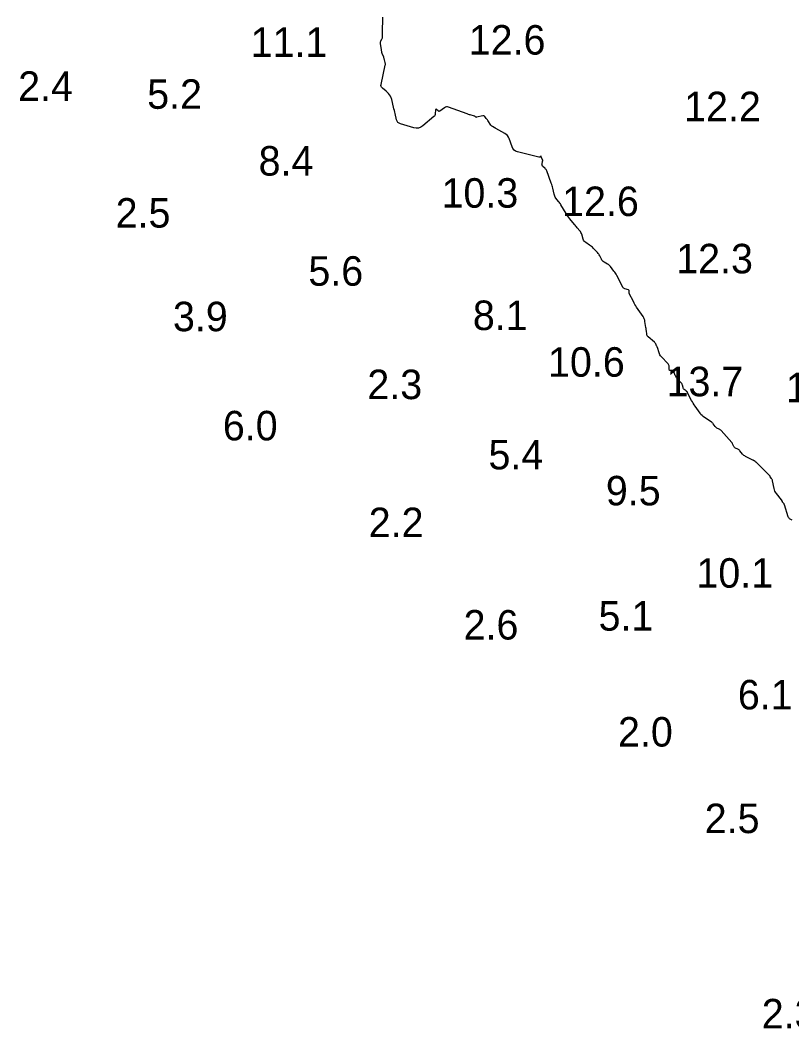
# Model space of a CAD drawing. Extents: x 815352 to 820877, y 582403 to 597439.
# Drawn here: x 819118.2 to 819249.1, y 593792.3 to 593963.3 of the extents above; entities that cross this region are included whole.
import ezdxf

# ---------------------------------------------------------------- set-up
doc = ezdxf.new("R2010")
doc.units = 0
doc.layers.add('V-CONT-EL12', color=7, linetype='Continuous')
doc.layers.add('V-TOPO-SOUN', color=7, linetype='Continuous')

msp = doc.modelspace()

# ---------------------------------------------------------------- linework, layer by layer
at = {"layer": 'V-CONT-EL12'}
msp.add_lwpolyline([(819249.13, 593878.51), (819248.72, 593878.76), (819248.63, 593878.83), (819248.56, 593878.9), (819248.5, 593878.99), (819248.46, 593879.09), (819247.83, 593881.13), (819247.81, 593881.18), (819247.79, 593881.23), (819247.76, 593881.28), (819247.73, 593881.32), (819247.56, 593881.52), (819247.54, 593881.56), (819247.51, 593881.59), (819247.49, 593881.63), (819247.48, 593881.67), (819247.42, 593881.83), (819247.4, 593881.87), (819247.38, 593881.91), (819247.36, 593881.94), (819247.34, 593881.98), (819246.47, 593883.05), (819246.33, 593883.24), (819246.22, 593883.45), (819246.13, 593883.67), (819246.07, 593883.9), (819245.81, 593885.19), (819245.79, 593885.29), (819245.75, 593885.38), (819245.71, 593885.47), (819245.66, 593885.55), (819245.44, 593885.88), (819245.39, 593885.97), (819245.33, 593886.04), (819245.26, 593886.12), (819245.19, 593886.19), (819243.07, 593888.28), (819243.03, 593888.32), (819242.98, 593888.36), (819242.93, 593888.4), (819242.88, 593888.44), (819242.68, 593888.58), (819242.63, 593888.62), (819242.58, 593888.65), (819242.52, 593888.68), (819242.47, 593888.71), (819241.24, 593889.32), (819241.1, 593889.4), (819240.97, 593889.49), (819240.85, 593889.59), (819240.74, 593889.71), (819240.27, 593890.28), (819240.2, 593890.36), (819240.12, 593890.43), (819240.03, 593890.49), (819239.93, 593890.54), (819239.53, 593890.73), (819239.44, 593890.78), (819239.37, 593890.84), (819239.31, 593890.92), (819239.26, 593891), (819239.1, 593891.36), (819239.05, 593891.45), (819239, 593891.53), (819238.95, 593891.61), (819238.89, 593891.69), (819237.11, 593893.69), (819237.03, 593893.77), (819236.95, 593893.84), (819236.86, 593893.9), (819236.77, 593893.95), (819236.38, 593894.13), (819236.29, 593894.19), (819236.2, 593894.25), (819236.13, 593894.32), (819236.06, 593894.4), (819235.76, 593894.83), (819235.68, 593894.93), (819235.6, 593895.02), (819235.51, 593895.1), (819235.41, 593895.17), (819234.28, 593895.92), (819234.06, 593896.08), (819233.87, 593896.26), (819233.68, 593896.45), (819233.52, 593896.66), (819232.67, 593897.86), (819232.52, 593898.09), (819232.37, 593898.32), (819232.23, 593898.56), (819232.1, 593898.81), (819231.42, 593900.1), (819231.37, 593900.19), (819231.31, 593900.27), (819231.24, 593900.34), (819231.17, 593900.41), (819230.85, 593900.66), (819230.78, 593900.72), (819230.72, 593900.8), (819230.68, 593900.88), (819230.65, 593900.98), (819230.54, 593901.4), (819230.51, 593901.5), (819230.47, 593901.59), (819230.42, 593901.68), (819230.35, 593901.76), (819229.65, 593902.53), (819229.55, 593902.64), (819229.46, 593902.77), (819229.39, 593902.9), (819229.33, 593903.04), (819229.06, 593903.74), (819229.02, 593903.81), (819228.97, 593903.85), (819228.91, 593903.88), (819228.83, 593903.89), (819228.48, 593903.87), (819228.41, 593903.88), (819228.35, 593903.9), (819228.32, 593903.96), (819228.31, 593904.03), (819228.3, 593904.58), (819228.29, 593904.7), (819228.25, 593904.81), (819228.2, 593904.91), (819228.13, 593905), (819226.95, 593906.25), (819226.83, 593906.39), (819226.73, 593906.54), (819226.65, 593906.7), (819226.58, 593906.87), (819226.29, 593907.76), (819226.26, 593907.84), (819226.23, 593907.92), (819226.2, 593908), (819226.16, 593908.08), (819226, 593908.4), (819225.96, 593908.47), (819225.91, 593908.54), (819225.85, 593908.61), (819225.79, 593908.67), (819224.73, 593909.57), (819224.64, 593909.67), (819224.56, 593909.78), (819224.51, 593909.9), (819224.49, 593910.03), (819224.42, 593910.59), (819224.4, 593910.73), (819224.38, 593910.87), (819224.36, 593911.01), (819224.34, 593911.15), (819224.18, 593912.2), (819224.14, 593912.42), (819224.07, 593912.62), (819223.97, 593912.82), (819223.86, 593913.01), (819222.77, 593914.59), (819222.61, 593914.82), (819222.47, 593915.06), (819222.33, 593915.3), (819222.21, 593915.55), (819221.52, 593916.95), (819221.5, 593917), (819221.49, 593917.06), (819221.48, 593917.11), (819221.48, 593917.17), (819221.49, 593917.39), (819221.49, 593917.44), (819221.47, 593917.48), (819221.44, 593917.51), (819221.39, 593917.54), (819220.78, 593917.73), (819220.67, 593917.77), (819220.57, 593917.84), (819220.49, 593917.92), (819220.42, 593918.02), (819219.39, 593920.01), (819219.28, 593920.2), (819219.17, 593920.38), (819219.05, 593920.56), (819218.92, 593920.73), (819218.33, 593921.49), (819218.22, 593921.62), (819218.1, 593921.73), (819217.97, 593921.84), (819217.83, 593921.93), (819217.25, 593922.26), (819217.11, 593922.35), (819216.99, 593922.46), (819216.89, 593922.58), (819216.81, 593922.73), (819216.51, 593923.32), (819216.43, 593923.46), (819216.34, 593923.6), (819216.24, 593923.73), (819216.13, 593923.86), (819215.4, 593924.64), (819215.26, 593924.78), (819215.11, 593924.91), (819214.96, 593925.03), (819214.8, 593925.14), (819214.14, 593925.58), (819213.99, 593925.69), (819213.87, 593925.83), (819213.77, 593925.99), (819213.7, 593926.17), (819213.45, 593926.97), (819213.39, 593927.13), (819213.32, 593927.28), (819213.23, 593927.43), (819213.13, 593927.56), (819212.69, 593928.09), (819212.58, 593928.22), (819212.47, 593928.36), (819212.36, 593928.49), (819212.25, 593928.62), (819211.43, 593929.61), (819211.26, 593929.82), (819211.1, 593930.04), (819210.95, 593930.26), (819210.8, 593930.49), (819209.94, 593931.95), (819209.84, 593932.11), (819209.74, 593932.26), (819209.64, 593932.4), (819209.53, 593932.55), (819209.07, 593933.11), (819208.97, 593933.26), (819208.88, 593933.42), (819208.82, 593933.58), (819208.77, 593933.75), (819208.54, 593934.76), (819208.49, 593934.99), (819208.43, 593935.21), (819208.36, 593935.43), (819208.28, 593935.65), (819207.52, 593937.7), (819207.47, 593937.82), (819207.41, 593937.93), (819207.33, 593938.03), (819207.25, 593938.13), (819206.82, 593938.54), (819206.77, 593938.61), (819206.73, 593938.68), (819206.71, 593938.76), (819206.72, 593938.85), (819206.8, 593939.38), (819206.81, 593939.39), (819206.81, 593939.4), (819206.82, 593939.41), (819206.83, 593939.42), (819206.87, 593939.45), (819206.88, 593939.46), (819206.88, 593939.47), (819206.89, 593939.48), (819206.88, 593939.49), (819206.65, 593939.96), (819206.63, 593939.98), (819206.62, 593940.01), (819206.61, 593940.03), (819206.6, 593940.06), (819206.57, 593940.16), (819206.56, 593940.18), (819206.55, 593940.19), (819206.53, 593940.19), (819206.51, 593940.18), (819206.35, 593940.06), (819206.32, 593940.03), (819206.28, 593940.02), (819206.24, 593940.02), (819206.2, 593940.02), (819202.56, 593940.95), (819202.25, 593941.07), (819201.99, 593941.25), (819201.79, 593941.49), (819201.65, 593941.79), (819201.16, 593943.18), (819201.04, 593943.45), (819200.87, 593943.7), (819200.66, 593943.91), (819200.41, 593944.08), (819198.91, 593944.92), (819198.83, 593944.96), (819198.76, 593945), (819198.68, 593945.04), (819198.61, 593945.08), (819198.3, 593945.24), (819198.23, 593945.28), (819198.17, 593945.34), (819198.11, 593945.39), (819198.06, 593945.46), (819197.52, 593946.26), (819197.46, 593946.35), (819197.4, 593946.43), (819197.34, 593946.51), (819197.27, 593946.6), (819197.02, 593946.92), (819196.95, 593946.99), (819196.87, 593947.03), (819196.78, 593947.05), (819196.69, 593947.04), (819195.61, 593946.8), (819195.58, 593946.79), (819195.55, 593946.8), (819195.52, 593946.81), (819195.5, 593946.83), (819195.4, 593946.93), (819195.38, 593946.95), (819195.35, 593946.97), (819195.32, 593946.98), (819195.29, 593946.99), (819194.54, 593947.19), (819194.41, 593947.22), (819194.27, 593947.26), (819194.14, 593947.31), (819194.01, 593947.36), (819190.88, 593948.52), (819190.7, 593948.56), (819190.52, 593948.56), (819190.35, 593948.52), (819190.19, 593948.43), (819189.38, 593947.86), (819189.31, 593947.82), (819189.24, 593947.81), (819189.17, 593947.83), (819189.1, 593947.88), (819188.83, 593948.13), (819188.77, 593948.17), (819188.72, 593948.18), (819188.69, 593948.14), (819188.68, 593948.07), (819188.61, 593947.39), (819188.59, 593947.25), (819188.54, 593947.12), (819188.46, 593947.01), (819188.36, 593946.91), (819186.52, 593945.34), (819186.16, 593945.1), (819185.79, 593944.97), (819185.39, 593944.94), (819184.97, 593945.01), (819182.72, 593945.68), (819182.48, 593945.79), (819182.29, 593945.93), (819182.16, 593946.13), (819182.07, 593946.37), (819181.8, 593947.43), (819181.74, 593947.69), (819181.68, 593947.96), (819181.61, 593948.22), (819181.55, 593948.49), (819181.24, 593949.84), (819181.2, 593949.98), (819181.15, 593950.11), (819181.08, 593950.24), (819181, 593950.36), (819180.66, 593950.82), (819180.57, 593950.94), (819180.48, 593951.04), (819180.38, 593951.14), (819180.27, 593951.24), (819179.64, 593951.76), (819179.52, 593951.88), (819179.44, 593952.02), (819179.41, 593952.18), (819179.43, 593952.35), (819180.13, 593955.61), (819180.15, 593955.73), (819180.15, 593955.84), (819180.14, 593955.96), (819180.12, 593956.07), (819180, 593956.53), (819179.97, 593956.64), (819179.94, 593956.75), (819179.9, 593956.87), (819179.87, 593956.98), (819179.63, 593957.63), (819179.58, 593957.78), (819179.54, 593957.93), (819179.5, 593958.08), (819179.48, 593958.23), (819179.32, 593959.32), (819179.31, 593959.42), (819179.32, 593959.52), (819179.34, 593959.61), (819179.38, 593959.7), (819179.58, 593960.09), (819179.62, 593960.17), (819179.64, 593960.25), (819179.66, 593960.33), (819179.66, 593960.42), (819179.67, 593960.76), (819179.67, 593960.84), (819179.68, 593960.93), (819179.68, 593961.01), (819179.68, 593961.1), (819179.73, 593963.78)], dxfattribs=at)

# ---------------------------------------------------------------- texts
at = {"layer": 'V-TOPO-SOUN'}
for s, p in [('12.6 ', (819194.29, 593957.43)), ('11.1 ', (819157.31, 593957.03)), ('2.4', (819117.88, 593949.59)), ('5.2', (819139.76, 593948.24)), ('12.2 ', (819230.82, 593946.14)), ('8.4', (819158.66, 593936.92)), ('10.3 ', (819189.68, 593931.48)), ('12.6 ', (819210.13, 593930.06)), ('2.5', (819134.41, 593928.1)), ('12.3 ', (819229.48, 593920.35)), ('5.6', (819167.1, 593918.25)), ('3.9', (819144.13, 593910.54)), ('8.1', (819194.99, 593910.74)), ('10.6 ', (819207.74, 593902.83)), ('2.3', (819177.1, 593899.03)), ('13.7 ', (819227.84, 593899.52)), ('12.5 ', (819248.08, 593898.5)), ('6.0', (819152.59, 593892.04)), ('5.4', (819197.64, 593887.12)), ('9.5', (819217.55, 593881.02)), ('2.2', (819177.33, 593875.64)), ('10.1 ', (819232.9, 593867.07)), ('5.1', (819216.31, 593859.79)), ('2.6', (819193.42, 593858.28)), ('6.1', (819239.93, 593846.44)), ('2.0', (819219.61, 593840.14)), ('2.5', (819234.32, 593825.47)), ('2.3', (819243.99, 593792.37))]:
    msp.add_text(s, height=5, dxfattribs=at).set_placement(p)

doc.saveas('drawing.dxf')
